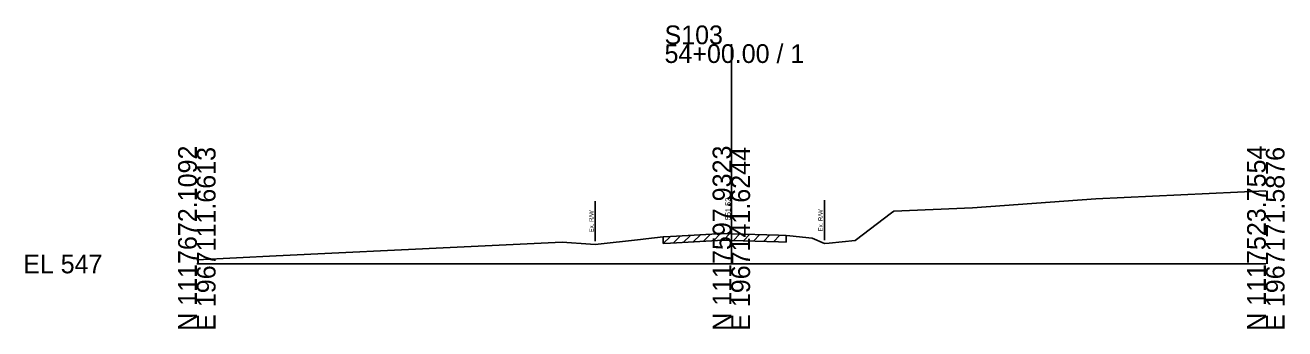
# Model space of a CAD drawing. Extents: x -26 to 163, y -10 to 24018.
# Drawn here: x -25.7 to 162.8, y 3490.3 to 3535.7 of the extents above; entities that cross this region are included whole.
import ezdxf

# ---------------------------------------------------------------- set-up
doc = ezdxf.new("R2010")
doc.units = 0
for name, color, linetype in [('RD_GPK_XS_Cell', 7, 'Continuous'), ('RD_XS_ExGround', 7, 'Continuous'), ('RD_XS_ExPaveRet', 7, 'Continuous'), ('RD_XS_ExRW', 7, 'Continuous'), ('RD_XS_TX_Elev_EX', 7, 'Continuous')]:
    doc.layers.add(name, color=color, linetype=linetype)

msp = doc.modelspace()

# ---------------------------------------------------------------- linework, layer by layer
at = {"layer": 'RD_GPK_XS_Cell'}
for p, q in [((80, 3500), (80, 3532.84)), ((0, 3500), (80, 3500)), ((80, 3500), (160, 3500))]:
    msp.add_line(p, q, dxfattribs=at)
at = {"layer": 'RD_XS_ExGround'}
msp.add_lwpolyline([(0, 3500.62), (11.85, 3501.23), (38.94, 3502.53), (54.67, 3503.27), (58.93, 3502.94), (59.62, 3502.88), (66.38, 3503.64), (67.22, 3503.74), (69.81, 3504.03), (70.9, 3504.1), (78.85, 3504.56), (80, 3504.52), (87.05, 3504.3), (88.23, 3504.27), (88.75, 3504.21), (92.1, 3503.85), (93.93, 3503.03), (94.62, 3503.08), (98.54, 3503.48), (103.97, 3507.63), (104.3, 3507.9), (116.09, 3508.38), (134.54, 3509.72), (160, 3510.95)], dxfattribs=at)
at = {"layer": 'RD_XS_ExPaveRet'}
for p, q in [((69.81, 3503.03), (70.88, 3504.1)), ((69.81, 3503.03), (69.81, 3504.03)), ((69.81, 3503.03), (70.9, 3503.1)), ((70.9, 3503.1), (78.85, 3503.56)), ((71.31, 3503.12), (72.37, 3504.19)), ((72.81, 3503.21), (73.87, 3504.27)), ((74.31, 3503.3), (75.37, 3504.36)), ((75.81, 3503.38), (76.87, 3504.44)), ((77.31, 3503.47), (78.37, 3504.53)), ((78.81, 3503.56), (79.79, 3504.53)), ((78.85, 3503.56), (80, 3503.52)), ((80, 3503.52), (87.05, 3503.3)), ((80.31, 3503.51), (81.28, 3504.48)), ((81.81, 3503.46), (82.78, 3504.43)), ((83.31, 3503.42), (84.28, 3504.39)), ((84.81, 3503.37), (85.78, 3504.34)), ((86.31, 3503.32), (87.28, 3504.29)), ((87.05, 3503.3), (88.23, 3503.27)), ((88.23, 3504.27), (88.23, 3503.27))]:
    msp.add_line(p, q, dxfattribs=at)
at = {"layer": 'RD_XS_ExRW'}
for p, q in [((59.62, 3509.38), (59.62, 3503.38)), ((93.93, 3509.53), (93.93, 3503.53))]:
    msp.add_line(p, q, dxfattribs=at)

# ---------------------------------------------------------------- texts
at = {"layer": 'RD_GPK_XS_Cell'}
for s, p in [('S103', (70, 3532.84)), ('54+00.00 / 1', (70, 3530.04)), ('EL 547', (-26, 3498.6))]:
    msp.add_text(s, height=2.8, dxfattribs=at).set_placement(p)
for s, p in [('N 1117672.1092', (0, 3490)), ('E 1967111.6613', (2.8, 3490)), ('N 1117597.9323', (80, 3490)), ('E 1967141.6244', (82.8, 3490)), ('N 1117523.7554', (160, 3490)), ('E 1967171.5876', (162.8, 3490))]:
    msp.add_text(s, height=2.8, rotation=90, dxfattribs=at).set_placement(p)
at = {"layer": 'RD_XS_ExRW'}
for p in [(59.37, 3504.73), (93.68, 3504.87)]:
    msp.add_text('Ex. R/W ', height=0.65, rotation=90, dxfattribs=at).set_placement(p)
at = {"layer": 'RD_XS_TX_Elev_EX'}
msp.add_text('551.52', height=0.8, rotation=90, dxfattribs=at).set_placement((79.9, 3506.52))

doc.saveas('drawing.dxf')
